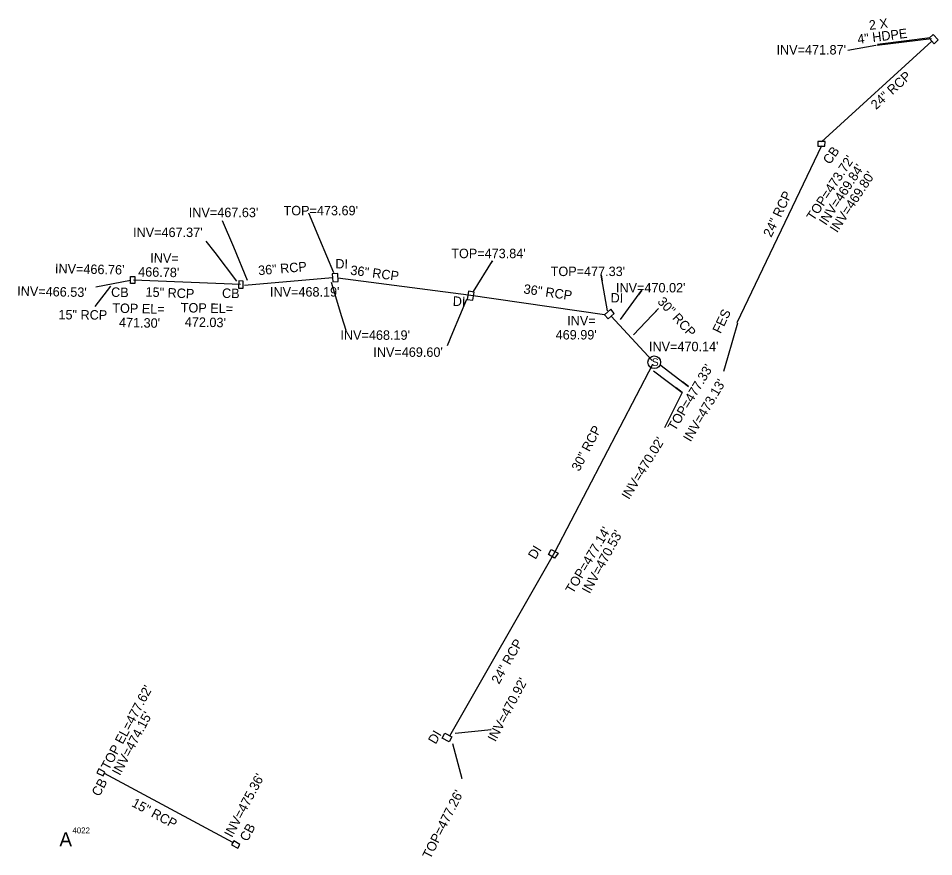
# Model space of a CAD drawing. Extents: x 1975859 to 1978323, y 778892 to 782836.
# Drawn here: x 1976024.4 to 1976411.8, y 779251.6 to 779606.7 of the extents above; entities that cross this region are included whole.
import ezdxf

# ---------------------------------------------------------------- set-up
doc = ezdxf.new("R2010")
doc.units = 0
for name, color, linetype in [('Exist Structure Minor Catch Basin', 7, 'Continuous'), ('Exist Structure Minor Catch Basin Text', 7, 'Continuous'), ('Exist Structure Minor Catch Basin Top Elevation', 7, 'Continuous'), ('Exist Structure Minor Drop Inlet', 7, 'Continuous'), ('Exist Structure Minor Drop Inlet Text', 7, 'Continuous'), ('Exist Structure Minor Drop Inlet Top Elevation', 7, 'Continuous'), ('Exist Structure Minor Pipes HDPE 8 Inch', 7, 'Continuous'), ('Exist Structure Minor Pipes HDPE 8 Inch Invert', 7, 'Continuous'), ('Exist Structure Minor Pipes HDPE 8 Inch Text', 7, 'Continuous'), ('Exist Structure Minor Pipes RCP 15 Inch', 7, 'Continuous'), ('Exist Structure Minor Pipes RCP 15 Inch Invert', 7, 'Continuous'), ('Exist Structure Minor Pipes RCP 15 Inch Leader', 7, 'Continuous'), ('Exist Structure Minor Pipes RCP 15 Inch Text', 7, 'Continuous'), ('Exist Structure Minor Pipes RCP 18 Inch Cogo Number', 7, 'Continuous'), ('Exist Structure Minor Pipes RCP 18 Inch Cogo Point CELL', 7, 'Continuous'), ('Exist Structure Minor Pipes RCP 24 Inch', 7, 'Continuous'), ('Exist Structure Minor Pipes RCP 24 Inch Invert', 7, 'Continuous'), ('Exist Structure Minor Pipes RCP 24 Inch Text', 7, 'Continuous'), ('Exist Structure Minor Pipes RCP 30 Inch', 7, 'Continuous'), ('Exist Structure Minor Pipes RCP 30 Inch Invert', 7, 'Continuous'), ('Exist Structure Minor Pipes RCP 30 Inch Text', 7, 'Continuous'), ('Exist Structure Minor Pipes RCP 36 Inch', 7, 'Continuous'), ('Exist Structure Minor Pipes RCP 36 Inch Invert', 7, 'Continuous'), ('Exist Structure Minor Pipes RCP 36 Inch Text', 7, 'Continuous'), ('Exist Structure Minor Storm Sewer Manhole CELL', 7, 'Continuous')]:
    doc.layers.add(name, color=color, linetype=linetype)

msp = doc.modelspace()

# ---------------------------------------------------------------- linework, layer by layer
at = {"layer": 'Exist Structure Minor Catch Basin'}
for p, q in [((1976071.89, 779497.38), (1976073.77, 779497.35)), ((1976117.62, 779492.39), (1976119.49, 779492.31)), ((1976057.68, 779287.19), (1976060.27, 779285.84)), ((1976114.64, 779256.69), (1976117.26, 779255.25))]:
    msp.add_line(p, q, dxfattribs=at)
msp.add_lwpolyline([(1976362.75, 779552.55), (1976365.76, 779552.52), (1976365.78, 779554.45), (1976362.77, 779554.48)], close=True, dxfattribs=at)
for points in [[(1976073.77, 779497.35), (1976073.73, 779494.31), (1976071.84, 779494.35), (1976071.89, 779497.38)], [(1976157.22, 779498.45), (1976157.47, 779495.06), (1976159.8, 779495.21), (1976159.57, 779498.59), (1976157.22, 779498.45)], [(1976119.49, 779492.31), (1976119.63, 779495.36), (1976117.7, 779495.47), (1976117.62, 779492.39)], [(1976060.27, 779285.84), (1976061.08, 779287.45), (1976058.52, 779288.8), (1976057.68, 779287.19)], [(1976117.26, 779255.25), (1976118.16, 779256.85), (1976115.56, 779258.34), (1976114.64, 779256.69)]]:
    msp.add_lwpolyline(points, dxfattribs=at)
at = {"layer": 'Exist Structure Minor Drop Inlet'}
msp.add_lwpolyline([(1976411.57, 779599.79), (1976413.7, 779597.5), (1976411.95, 779595.88), (1976409.83, 779598.18)], close=True, dxfattribs=at)
for points in [[(1976214.86, 779491.06), (1976214.36, 779487.57), (1976216.7, 779487.29), (1976217.25, 779490.65), (1976214.86, 779491.06)], [(1976275.15, 779483.49), (1976272.53, 779481.12), (1976274.01, 779479.43), (1976276.58, 779481.61), (1976275.15, 779483.49)], [(1976249.9, 779381.67), (1976252.83, 779380.1), (1976251.37, 779378.1), (1976248.76, 779379.62), (1976249.9, 779381.67)], [(1976203.78, 779301.9), (1976204.9, 779303.97), (1976207.89, 779302.42), (1976206.76, 779300.3), (1976203.78, 779301.9)]]:
    msp.add_lwpolyline(points, dxfattribs=at)
at = {"layer": 'Exist Structure Minor Drop Inlet Text'}
msp.add_lwpolyline([(1976387.23, 779595.12), (1976375.43, 779592.99)], dxfattribs=at)
at = {"layer": 'Exist Structure Minor Pipes HDPE 8 Inch'}
for points in [[(1976387.7, 779595.25), (1976410.78, 779598.11)], [(1976387.98, 779595.75), (1976410.25, 779598.52)]]:
    msp.add_lwpolyline(points, dxfattribs=at)
at = {"layer": 'Exist Structure Minor Pipes RCP 15 Inch'}
for p, q in [((1976071.86, 779495.6), (1976057.28, 779492.77)), ((1976118.37, 779493.91), (1976073.09, 779495.83)), ((1976115.18, 779257.69), (1976060.87, 779286.83))]:
    msp.add_line(p, q, dxfattribs=at)
at = {"layer": 'Exist Structure Minor Pipes RCP 15 Inch Leader'}
msp.add_lwpolyline([(1976063.35, 779493.17), (1976056.73, 779484.68)], dxfattribs=at)
at = {"layer": 'Exist Structure Minor Pipes RCP 24 Inch'}
for p, q in [((1976411.03, 779596.94), (1976364.25, 779554.37)), ((1976364.27, 779552.66), (1976328.4, 779477.77))]:
    msp.add_line(p, q, dxfattribs=at)
msp.add_lwpolyline([(1976206.96, 779302.85), (1976251.46, 779380.6)], dxfattribs=at)
at = {"layer": 'Exist Structure Minor Pipes RCP 24 Inch Invert'}
for points in [[(1976157.9, 779498.87), (1976152.06, 779513.01), (1976147.29, 779524.17)], [(1976121.44, 779495.59), (1976115.6, 779509.73), (1976110.83, 779520.89)], [(1976116.9, 779495.32), (1976107.65, 779507.5), (1976103.96, 779512.24)], [(1976217.07, 779490.97), (1976225.08, 779504.01), (1976224.43, 779502.93)], [(1976273.77, 779482.81), (1976271.08, 779497.87), (1976271.52, 779495.53)], [(1976156.76, 779494.98), (1976161.15, 779480.32), (1976162.94, 779474.59)], [(1976279.27, 779479.17), (1976288.26, 779491.56), (1976286.88, 779489.61)], [(1976214.1, 779487.61), (1976208.15, 779473.52), (1976205.89, 779467.96)], [(1976284.71, 779472.66), (1976295.28, 779483.72), (1976293.66, 779481.97)], [(1976328.68, 779477.62), (1976324.46, 779462.92), (1976322.88, 779457.13)], [(1976295.82, 779459.99), (1976308.04, 779450.79), (1976305.43, 779452.71)], [(1976293.14, 779457.41), (1976305.37, 779448.21), (1976302.75, 779450.13)], [(1976209.24, 779303.97), (1976224.46, 779305.56), (1976224.3, 779305.54)], [(1976208.17, 779299.54), (1976212.14, 779284.76), (1976212.1, 779284.92)]]:
    msp.add_lwpolyline(points, dxfattribs=at)
at = {"layer": 'Exist Structure Minor Pipes RCP 30 Inch'}
msp.add_line((1976251.46, 779380.6), (1976292.89, 779460.21), dxfattribs=at)
msp.add_lwpolyline([(1976292.58, 779461.78), (1976275.27, 779480.59)], dxfattribs=at)
at = {"layer": 'Exist Structure Minor Pipes RCP 36 Inch'}
for points in [[(1976157.36, 779496.74), (1976120.17, 779493.52)], [(1976272.47, 779481.15), (1976214.96, 779489.36), (1976159.67, 779496.56)]]:
    msp.add_lwpolyline(points, dxfattribs=at)
at = {"layer": 'Exist Structure Minor Pipes RCP 36 Inch Invert'}
msp.add_line((1976305.37, 779448.21), (1976297.82, 779433.2), dxfattribs=at)
at = {"layer": 'Exist Structure Minor Storm Sewer Manhole CELL'}
msp.add_circle((1976293.51, 779461.02), 2.69, dxfattribs=at)

# ---------------------------------------------------------------- texts
at = {"layer": 'Exist Structure Minor Catch Basin Text'}
for s, rotation, p in [('CB', 54.8658, (1976367.85, 779544.47)), ("TOP=473.72'", 56.5752, (1976361.01, 779520.57)), ('DI', 358.8319, (1976158.53, 779500.74)), ('CB', 358.8319, (1976063.63, 779488.73)), ('CB', 358.8319, (1976110.58, 779488.29)), ('DI', 358.8319, (1976275.01, 779486.35)), ('DI', 358.8319, (1976208.24, 779484.89)), ('DI', 58.6905, (1976243.25, 779377.24)), ('DI', 59.4429, (1976200.99, 779298.99)), ('CB', 61.9141, (1976058.73, 779276.85)), ('CB', 61.9141, (1976121.4, 779257.79))]:
    msp.add_text(s, height=4, rotation=rotation, dxfattribs=at).set_placement(p)
at = {"layer": 'Exist Structure Minor Catch Basin Top Elevation'}
for s, rotation, p in [("TOP=473.69'", 0, (1976136.65, 779523.24)), ('TOP EL=', 358.8319, (1976064.15, 779481.97)), ('TOP EL=', 358.8319, (1976093.12, 779482.18)), ("471.30'", 358.8319, (1976066.98, 779475.91)), ("472.03'", 358.8319, (1976094.83, 779476.14)), ("TOP EL=477.62'", 61.9141, (1976062.7, 779287.96))]:
    msp.add_text(s, height=4, rotation=rotation, dxfattribs=at).set_placement(p)
at = {"layer": 'Exist Structure Minor Drop Inlet Top Elevation'}
for s, rotation, p in [("TOP=473.84'", 0, (1976207.62, 779505.08)), ("TOP=477.33'", 0, (1976249.69, 779497.5)), ("TOP=477.14'", 59.2159, (1976259.12, 779362.72)), ("TOP=477.26'", 63.4349, (1976198.79, 779250.4))]:
    msp.add_text(s, height=4, rotation=rotation, dxfattribs=at).set_placement(p)
at = {"layer": 'Exist Structure Minor Pipes HDPE 8 Inch Invert'}
msp.add_text("INV=471.87'", height=4, rotation=0, dxfattribs=at).set_placement((1976345.25, 779591.32))
at = {"layer": 'Exist Structure Minor Pipes HDPE 8 Inch Text'}
for s, p in [('2 X', (1976384.63, 779601.71)), ('4" HDPE', (1976379.74, 779595.79))]:
    msp.add_text(s, height=4, rotation=7.1058, dxfattribs=at).set_placement(p)
at = {"layer": 'Exist Structure Minor Pipes RCP 15 Inch Invert'}
for s, rotation, p in [("INV=467.37'", 0, (1976072.96, 779514.02)), ('INV=', 358.8319, (1976080.2, 779503.25)), ("INV=466.76'", 358.8319, (1976039.88, 779498.73)), ("466.78'", 358.8319, (1976075.1, 779497.35)), ("INV=466.53'", 358.8319, (1976023.91, 779489.22)), ("INV=474.15'", 61.9141, (1976067.37, 779285.73)), ("INV=475.36'", 61.9141, (1976114.84, 779259.49))]:
    msp.add_text(s, height=4, rotation=rotation, dxfattribs=at).set_placement(p)
at = {"layer": 'Exist Structure Minor Pipes RCP 15 Inch Text'}
for rotation, p in [(357.5639, (1976078.19, 779488.86)), (359.6654, (1976041.39, 779479.17)), (331.7801, (1976072.05, 779273.17))]:
    msp.add_text('15" RCP', height=4, rotation=rotation, dxfattribs=at).set_placement(p)
at = {"layer": 'Exist Structure Minor Pipes RCP 18 Inch Cogo Number'}
msp.add_text('4022', height=2.5, dxfattribs=at).set_placement((1976047.29, 779261.51))
at = {"layer": 'Exist Structure Minor Pipes RCP 18 Inch Cogo Point CELL'}
msp.add_text('A', height=6, dxfattribs=at).set_placement((1976041.79, 779256.01))
at = {"layer": 'Exist Structure Minor Pipes RCP 24 Inch Invert'}
for s, rotation, p in [("INV=469.84'", 56.5752, (1976366.23, 779518.66)), ("INV=469.80'", 56.5752, (1976370.88, 779515.59)), ("INV=473.13'", 59.3646, (1976308.91, 779427.02)), ("INV=470.92'", 62.133, (1976226.3, 779300.02))]:
    msp.add_text(s, height=4, rotation=rotation, dxfattribs=at).set_placement(p)
at = {"layer": 'Exist Structure Minor Pipes RCP 24 Inch Text'}
for s, rotation, p in [('24" RCP', 42.2984, (1976387.37, 779567.76)), ('24" RCP', 64.4089, (1976343.02, 779513.64)), ('FES', 64.4089, (1976321.58, 779472.89)), ('24" RCP', 60.2206, (1976227.82, 779324.42))]:
    msp.add_text(s, height=4, rotation=rotation, dxfattribs=at).set_placement(p)
at = {"layer": 'Exist Structure Minor Pipes RCP 30 Inch Invert'}
for s, rotation, p in [("TOP=477.33'", 59.0363, (1976302.37, 779431.62)), ("INV=470.02'", 58.634, (1976282.8, 779402.61)), ("INV=470.53'", 61.321, (1976266.19, 779362.71))]:
    msp.add_text(s, height=4, rotation=rotation, dxfattribs=at).set_placement(p)
at = {"layer": 'Exist Structure Minor Pipes RCP 30 Inch Text'}
for rotation, p in [(312.631, (1976294.61, 779486.46)), (62.5044, (1976261.8, 779414.55))]:
    msp.add_text('30" RCP', height=4, rotation=rotation, dxfattribs=at).set_placement(p)
at = {"layer": 'Exist Structure Minor Pipes RCP 36 Inch Invert'}
for s, p in [("INV=467.63'", (1976096.55, 779522.44)), ("INV=470.02'", (1976277.32, 779490.57)), ("INV=468.19'", (1976130.9, 779488.82)), ('INV=', (1976256.68, 779476.65)), ("INV=468.19'", (1976160.72, 779470.51)), ("469.99'", (1976251.8, 779470.65)), ("INV=469.60'", (1976174.64, 779463.29)), ("INV=470.14'", (1976291.29, 779465.67))]:
    msp.add_text(s, height=4, rotation=0, dxfattribs=at).set_placement(p)
at = {"layer": 'Exist Structure Minor Pipes RCP 36 Inch Text'}
for rotation, p in [(4.9491, (1976126.08, 779497.85)), (352.5758, (1976164.75, 779498.12)), (351.8809, (1976238.03, 779490.17))]:
    msp.add_text('36" RCP', height=4, rotation=rotation, dxfattribs=at).set_placement(p)
at = {"layer": 'Exist Structure Minor Storm Sewer Manhole CELL'}
msp.add_text('S', height=3.25, dxfattribs=at).set_placement((1976292.48, 779459.42))

doc.saveas('drawing.dxf')
